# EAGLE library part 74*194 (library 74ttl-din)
4-bit bidirectional SHIFT REGISTER
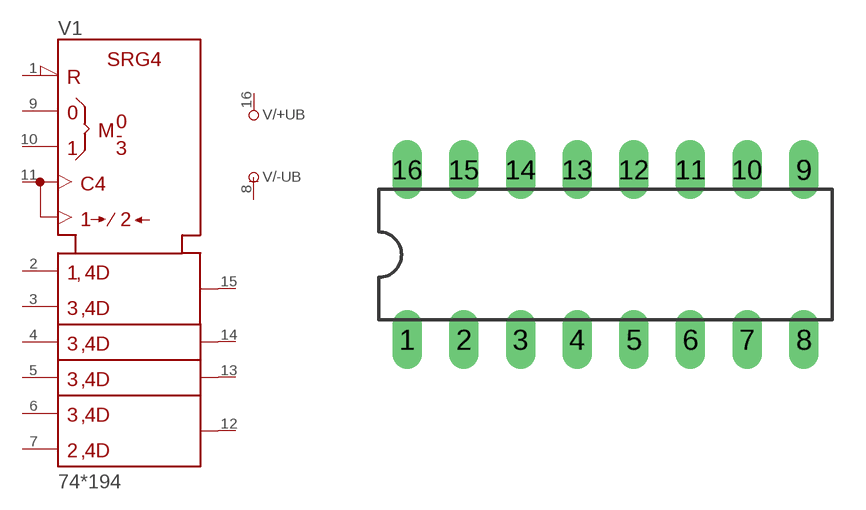
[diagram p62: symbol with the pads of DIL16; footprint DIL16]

Designator prefix V; gates /+UB=+UB /-UB=-UB 1=194

## 74194N  [DIL16]
1  1:CLR\  in
2  1:SR_SER  in
3  1:A  in
4  1:B  in
5  1:C  in
6  1:D  in
7  1:SL_SER  in
8  /-UB:-UB  pwr
9  1:S0  in
10  1:S1  in
11  1:CLK  in
12  1:QD  out
13  1:QC  out
14  1:QB  out
15  1:QA  out
16  /+UB:+UB  pwr

## Footprint DIL16 (pad centres in mm)
Dual In Line Package
drill 0.813 long: 1 -8.89,-3.81; 2 -6.35,-3.81; 3 -3.81,-3.81; 4 -1.27,-3.81; 5 1.27,-3.81; 6 3.81,-3.81; 7 6.35,-3.81; 8 8.89,-3.81; 9 8.89,3.81; 10 6.35,3.81; 11 3.81,3.81; 12 1.27,3.81; 13 -1.27,3.81; 14 -3.81,3.81; 15 -6.35,3.81; 16 -8.89,3.81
